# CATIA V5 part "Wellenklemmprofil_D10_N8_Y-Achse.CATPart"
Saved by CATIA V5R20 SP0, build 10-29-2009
Part number: Wellenklemmprofil_D10_N8_Y-Achse_Unten
Bounding box of the stored display mesh (mm): x 0 to 760, y -9 to 9, z -12 to 15
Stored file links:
  C:\Users\Andi\Desktop\Plasma\Wellenklemmprofil_D10_N8_Y-Achse.CATPart
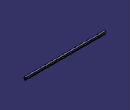
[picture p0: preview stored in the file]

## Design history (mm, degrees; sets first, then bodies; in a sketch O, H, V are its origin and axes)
Body1 (main body)
  Sketch1 on yz-plane, origin (0, 0, 0), H (0, 1, 0), V (0, 0, 1)
    line L1 (-9, 10) -> (-9, 0)
    point P2 (-9, 0)
    line L2 (-9, 0) -> (-4, 0)
    line L3 (-4, 0) -> (-4, -12)
    line L4 (-4, -12) -> (4, -12)
    line L5 (4, -12) -> (4, 0)
    point P6 (4, 0)
    line L6 (4, 0) -> (9, 0)
    line L7 (9, 0) -> (9, 10)
    line L8 (9, 10) -> (7.0993, 10)
    line L9 (-9, 10) -> (-7.0993, 10)
    arc A1 centre (0, 8) radius 7 from (-6.8075, 9.6301) to (6.8075, 9.6301) ccw
    point P9 (0, 8)
    arc A2 centre (-7.0993, 9.7) radius 0.3 from (-6.8075, 9.6301) to (-7.0993, 10) ccw
    arc A3 centre (7.0993, 9.7) radius 0.3 from (6.8075, 9.6301) to (7.0993, 10) cw
    radius A1 = 7
    distance L6 L8 = 10
    distance L7 L1 = 18
    radius A2 = 0.3
    radius A3 = 0.3 {= Sketch1.radius(A2)}
    distance P9 L6 = 8
    distance L8 L4 = 22
    distance L5 L3 = 8
    coincidence: P2 H, P6 H, P9 V, L9 L8
    vertical: L1 V, L3 V, L5 V, L7 V
    horizontal: L2 H, L4 H, L6 H, L8 H, L9 H
    symmetry: L7 L1 V, L3 L5 V
    tangency: A2 A1, A2 L9, A3 A1, A3 L8
  Pad1: profile Sketch1, direction (1, 0, 0), length 760
  Fillet1: radius 0.3, on edge [face of Pad1 from Sketch1.L8 | face of Pad1 from Sketch1.L7]; edge [face of Pad1 from Sketch1.L1 | face of Pad1 from Sketch1.L9]
Body2
  Sketch2 on yz-plane, origin (0, 0, 0), H (0, 1, 0), V (0, 0, 1)
    circle A1 centre (0, 8) radius 7
    reference projected arc E1 centre (0, 8) radius 7 from (-6.8182, 9.5849) to (6.8182, 9.5849) ccw from edge [face of Pad1 from Sketch1.A1 | end face of Pad1]
    coincidence: A1 E1
  Pad2: profile Sketch2, direction (1, 0, 0), length 760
